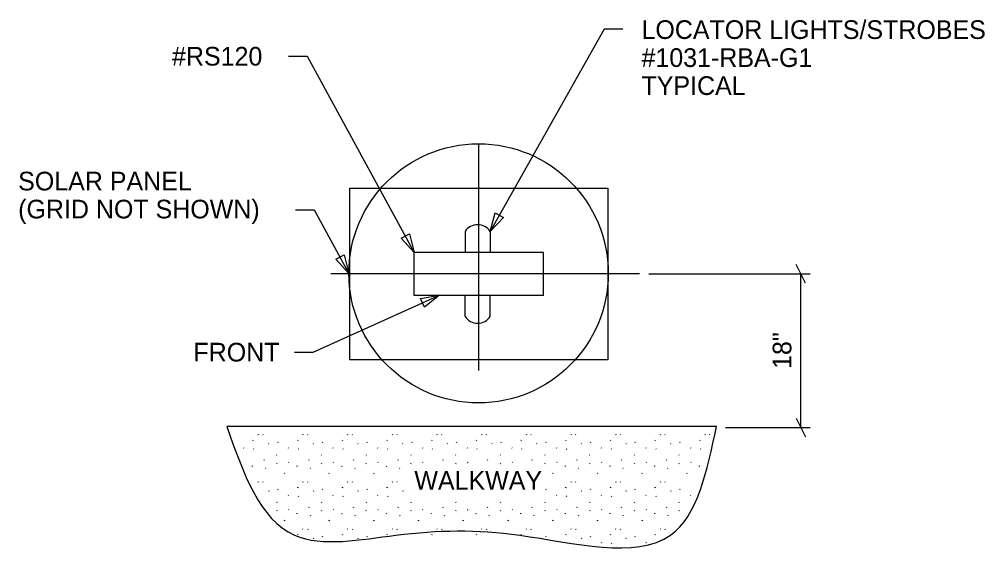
# Model space of a CAD drawing. Extents: x 10097.7 to 10174.5, y 10050.6 to 10139.4.
# Drawn here: x 10101.45 to 10135.89, y 10120.08 to 10139.38 of the extents above; entities that cross this region are included whole.
import ezdxf

# ---------------------------------------------------------------- set-up
doc = ezdxf.new("R2010")
doc.units = 0
for name, color, linetype in [('Level 57', 7, 'Continuous'), ('Level 60', 7, 'Continuous'), ('Level 61', 7, 'Continuous'), ('Level 62', 7, 'Continuous'), ('Level 63', 7, 'Continuous')]:
    doc.layers.add(name, color=color, linetype=linetype)

msp = doc.modelspace()

# ---------------------------------------------------------------- linework, layer by layer
at = {"layer": 'Level 57'}
for p, q in [((10129.491, 10129.949), (10129.157, 10130.616)), ((10123.902, 10130.282), (10129.657, 10130.282)), ((10129.324, 10124.803), (10129.324, 10130.282)), ((10129.157, 10125.136), (10129.491, 10124.47)), ((10126.642, 10124.803), (10129.657, 10124.803))]:
    msp.add_line(p, q, dxfattribs=at)
at = {"layer": 'Level 60'}
for p, q in [((10126.323, 10124.837), (10108.845, 10124.837)), ((10109.783, 10124.333), (10109.795, 10124.36)), ((10109.96, 10124.555), (10109.972, 10124.537)), ((10110.13, 10124.548), (10110.142, 10124.53)), ((10111.377, 10124.333), (10111.389, 10124.36)), ((10111.554, 10124.555), (10111.566, 10124.537)), ((10111.725, 10124.548), (10111.737, 10124.53)), ((10112.972, 10124.333), (10112.984, 10124.36)), ((10113.148, 10124.555), (10113.16, 10124.537)), ((10113.319, 10124.548), (10113.331, 10124.53)), ((10114.566, 10124.333), (10114.578, 10124.36)), ((10114.743, 10124.555), (10114.755, 10124.537)), ((10114.913, 10124.548), (10114.925, 10124.53)), ((10116.16, 10124.333), (10116.172, 10124.36)), ((10116.337, 10124.555), (10116.349, 10124.537)), ((10116.508, 10124.548), (10116.52, 10124.53)), ((10117.755, 10124.333), (10117.767, 10124.36)), ((10117.931, 10124.555), (10117.943, 10124.537)), ((10118.102, 10124.548), (10118.114, 10124.53)), ((10119.349, 10124.333), (10119.361, 10124.36)), ((10119.526, 10124.555), (10119.538, 10124.537)), ((10119.696, 10124.548), (10119.708, 10124.53)), ((10120.943, 10124.333), (10120.955, 10124.36)), ((10121.12, 10124.555), (10121.132, 10124.537)), ((10121.291, 10124.548), (10121.303, 10124.53)), ((10122.538, 10124.333), (10122.55, 10124.36)), ((10122.714, 10124.555), (10122.726, 10124.537)), ((10122.885, 10124.548), (10122.897, 10124.53)), ((10124.132, 10124.333), (10124.144, 10124.36)), ((10124.309, 10124.555), (10124.321, 10124.537)), ((10124.479, 10124.548), (10124.491, 10124.53)), ((10125.726, 10124.333), (10125.738, 10124.36)), ((10125.903, 10124.555), (10125.915, 10124.537)), ((10126.074, 10124.548), (10126.086, 10124.53)), ((10109.447, 10124.072), (10109.459, 10124.054)), ((10109.801, 10124.04), (10109.813, 10124.022)), ((10110.332, 10124.229), (10110.344, 10124.211)), ((10110.667, 10124.264), (10110.679, 10124.291)), ((10111.042, 10124.072), (10111.054, 10124.054)), ((10111.396, 10124.04), (10111.408, 10124.022)), ((10111.926, 10124.229), (10111.938, 10124.211)), ((10112.261, 10124.264), (10112.273, 10124.291)), ((10112.636, 10124.072), (10112.648, 10124.054)), ((10112.99, 10124.04), (10113.002, 10124.022)), ((10113.52, 10124.229), (10113.532, 10124.211)), ((10113.856, 10124.264), (10113.868, 10124.291)), ((10114.23, 10124.072), (10114.242, 10124.054)), ((10114.584, 10124.04), (10114.596, 10124.022)), ((10115.115, 10124.229), (10115.127, 10124.211)), ((10115.45, 10124.264), (10115.462, 10124.291)), ((10115.825, 10124.072), (10115.837, 10124.054)), ((10116.179, 10124.04), (10116.191, 10124.022)), ((10116.709, 10124.229), (10116.721, 10124.211)), ((10117.044, 10124.264), (10117.056, 10124.291)), ((10117.419, 10124.072), (10117.431, 10124.054)), ((10117.773, 10124.04), (10117.785, 10124.022)), ((10118.303, 10124.229), (10118.315, 10124.211)), ((10118.639, 10124.264), (10118.651, 10124.291)), ((10119.013, 10124.072), (10119.025, 10124.054)), ((10119.367, 10124.04), (10119.379, 10124.022)), ((10119.898, 10124.229), (10119.91, 10124.211)), ((10120.233, 10124.264), (10120.245, 10124.291)), ((10120.608, 10124.072), (10120.62, 10124.054)), ((10120.962, 10124.04), (10120.974, 10124.022)), ((10121.492, 10124.229), (10121.504, 10124.211)), ((10121.827, 10124.264), (10121.839, 10124.291)), ((10122.202, 10124.072), (10122.214, 10124.054)), ((10122.556, 10124.04), (10122.568, 10124.022)), ((10123.086, 10124.229), (10123.098, 10124.211)), ((10123.422, 10124.264), (10123.434, 10124.291)), ((10123.796, 10124.072), (10123.808, 10124.054)), ((10124.15, 10124.04), (10124.162, 10124.022)), ((10124.681, 10124.229), (10124.693, 10124.211)), ((10125.016, 10124.264), (10125.028, 10124.291)), ((10125.391, 10124.072), (10125.403, 10124.054)), ((10125.745, 10124.04), (10125.757, 10124.022)), ((10110.181, 10123.626), (10110.193, 10123.653)), ((10110.627, 10123.827), (10110.639, 10123.809)), ((10111.776, 10123.626), (10111.788, 10123.653)), ((10112.221, 10123.827), (10112.233, 10123.809)), ((10113.37, 10123.626), (10113.382, 10123.653)), ((10113.816, 10123.827), (10113.828, 10123.809)), ((10114.964, 10123.626), (10114.976, 10123.653)), ((10115.41, 10123.827), (10115.422, 10123.809)), ((10116.559, 10123.626), (10116.571, 10123.653)), ((10117.004, 10123.827), (10117.016, 10123.809)), ((10118.153, 10123.626), (10118.165, 10123.653)), ((10118.599, 10123.827), (10118.611, 10123.809)), ((10119.747, 10123.626), (10119.759, 10123.653)), ((10120.193, 10123.827), (10120.205, 10123.809)), ((10121.342, 10123.626), (10121.354, 10123.653)), ((10121.787, 10123.827), (10121.799, 10123.809)), ((10122.936, 10123.626), (10122.948, 10123.653)), ((10123.382, 10123.827), (10123.394, 10123.809)), ((10124.53, 10123.626), (10124.542, 10123.653)), ((10124.976, 10123.827), (10124.988, 10123.809)), ((10109.755, 10123.428), (10109.758, 10123.401)), ((10110.225, 10123.348), (10110.237, 10123.33)), ((10110.637, 10123.503), (10110.649, 10123.53)), ((10111.053, 10123.561), (10111.065, 10123.543)), ((10111.35, 10123.428), (10111.353, 10123.401)), ((10111.819, 10123.348), (10111.831, 10123.33)), ((10112.231, 10123.503), (10112.243, 10123.53)), ((10112.647, 10123.561), (10112.659, 10123.543)), ((10112.944, 10123.428), (10112.947, 10123.401)), ((10113.414, 10123.348), (10113.426, 10123.33)), ((10113.826, 10123.503), (10113.838, 10123.53)), ((10114.242, 10123.561), (10114.254, 10123.543)), ((10114.538, 10123.428), (10114.541, 10123.401)), ((10115.008, 10123.348), (10115.02, 10123.33)), ((10115.42, 10123.503), (10115.432, 10123.53)), ((10115.836, 10123.561), (10115.848, 10123.543)), ((10117.014, 10123.503), (10117.026, 10123.53)), ((10117.43, 10123.561), (10117.442, 10123.543)), ((10118.609, 10123.503), (10118.621, 10123.53)), ((10119.025, 10123.561), (10119.037, 10123.543)), ((10120.203, 10123.503), (10120.215, 10123.53)), ((10120.619, 10123.561), (10120.631, 10123.543)), ((10120.916, 10123.428), (10120.919, 10123.401)), ((10121.385, 10123.348), (10121.397, 10123.33)), ((10121.797, 10123.503), (10121.809, 10123.53)), ((10122.213, 10123.561), (10122.225, 10123.543)), ((10122.51, 10123.428), (10122.513, 10123.401)), ((10122.98, 10123.348), (10122.992, 10123.33)), ((10123.392, 10123.503), (10123.404, 10123.53)), ((10123.808, 10123.561), (10123.82, 10123.543)), ((10124.104, 10123.428), (10124.107, 10123.401)), ((10124.574, 10123.348), (10124.586, 10123.33)), ((10124.986, 10123.503), (10124.998, 10123.53)), ((10125.402, 10123.561), (10125.414, 10123.543)), ((10125.699, 10123.428), (10125.702, 10123.401)), ((10110.91, 10123.155), (10110.922, 10123.182)), ((10112.504, 10123.155), (10112.516, 10123.182)), ((10114.098, 10123.155), (10114.11, 10123.182)), ((10120.476, 10123.155), (10120.488, 10123.182)), ((10122.07, 10123.155), (10122.082, 10123.182)), ((10123.664, 10123.155), (10123.676, 10123.182)), ((10125.259, 10123.155), (10125.271, 10123.182)), ((10109.96, 10122.869), (10109.972, 10122.851)), ((10110.13, 10122.862), (10110.142, 10122.844)), ((10110.667, 10122.578), (10110.679, 10122.605)), ((10111.377, 10122.647), (10111.389, 10122.674)), ((10111.554, 10122.869), (10111.566, 10122.851)), ((10111.725, 10122.862), (10111.737, 10122.844)), ((10112.261, 10122.578), (10112.273, 10122.605)), ((10112.972, 10122.647), (10112.984, 10122.674)), ((10113.148, 10122.869), (10113.16, 10122.851)), ((10113.319, 10122.862), (10113.331, 10122.844)), ((10113.856, 10122.578), (10113.868, 10122.605)), ((10114.566, 10122.647), (10114.578, 10122.674)), ((10114.743, 10122.869), (10114.755, 10122.851)), ((10114.913, 10122.862), (10114.925, 10122.844)), ((10120.233, 10122.578), (10120.245, 10122.605)), ((10120.943, 10122.647), (10120.955, 10122.674)), ((10121.12, 10122.869), (10121.132, 10122.851)), ((10121.291, 10122.862), (10121.303, 10122.844)), ((10121.827, 10122.578), (10121.839, 10122.605)), ((10122.538, 10122.647), (10122.55, 10122.674)), ((10122.714, 10122.869), (10122.726, 10122.851)), ((10122.885, 10122.862), (10122.897, 10122.844)), ((10123.422, 10122.578), (10123.434, 10122.605)), ((10124.132, 10122.647), (10124.144, 10122.674)), ((10124.309, 10122.869), (10124.321, 10122.851)), ((10124.479, 10122.862), (10124.491, 10122.844)), ((10125.016, 10122.578), (10125.028, 10122.605)), ((10110.332, 10122.543), (10110.344, 10122.525)), ((10111.042, 10122.386), (10111.054, 10122.368)), ((10111.396, 10122.353), (10111.408, 10122.335)), ((10111.926, 10122.543), (10111.938, 10122.525)), ((10112.636, 10122.386), (10112.648, 10122.368)), ((10112.99, 10122.353), (10113.002, 10122.335)), ((10113.52, 10122.543), (10113.532, 10122.525)), ((10114.23, 10122.386), (10114.242, 10122.368)), ((10114.584, 10122.353), (10114.596, 10122.335)), ((10115.115, 10122.543), (10115.127, 10122.525)), ((10120.608, 10122.386), (10120.62, 10122.368)), ((10120.962, 10122.353), (10120.974, 10122.335)), ((10121.492, 10122.543), (10121.504, 10122.525)), ((10122.202, 10122.386), (10122.214, 10122.368)), ((10122.556, 10122.353), (10122.568, 10122.335)), ((10123.086, 10122.543), (10123.098, 10122.525)), ((10123.796, 10122.386), (10123.808, 10122.368)), ((10124.15, 10122.353), (10124.162, 10122.335)), ((10124.681, 10122.543), (10124.693, 10122.525)), ((10125.391, 10122.386), (10125.403, 10122.368)), ((10110.627, 10122.141), (10110.639, 10122.123)), ((10111.776, 10121.939), (10111.788, 10121.966)), ((10112.221, 10122.141), (10112.233, 10122.123)), ((10113.37, 10121.939), (10113.382, 10121.966)), ((10113.816, 10122.141), (10113.828, 10122.123)), ((10114.964, 10121.939), (10114.976, 10121.966)), ((10115.41, 10122.141), (10115.422, 10122.123)), ((10116.559, 10121.939), (10116.571, 10121.966)), ((10117.004, 10122.141), (10117.016, 10122.123)), ((10118.153, 10121.939), (10118.165, 10121.966)), ((10118.599, 10122.141), (10118.611, 10122.123)), ((10119.747, 10121.939), (10119.759, 10121.966)), ((10120.193, 10122.141), (10120.205, 10122.123)), ((10121.342, 10121.939), (10121.354, 10121.966)), ((10121.787, 10122.141), (10121.799, 10122.123)), ((10122.936, 10121.939), (10122.948, 10121.966)), ((10123.382, 10122.141), (10123.394, 10122.123)), ((10124.53, 10121.939), (10124.542, 10121.966)), ((10124.976, 10122.141), (10124.988, 10122.123)), ((10110.637, 10121.816), (10110.649, 10121.843)), ((10111.053, 10121.875), (10111.065, 10121.857)), ((10111.35, 10121.741), (10111.353, 10121.714)), ((10111.819, 10121.662), (10111.831, 10121.644)), ((10112.231, 10121.816), (10112.243, 10121.843)), ((10112.647, 10121.875), (10112.659, 10121.857)), ((10112.944, 10121.741), (10112.947, 10121.714)), ((10113.414, 10121.662), (10113.426, 10121.644)), ((10113.826, 10121.816), (10113.838, 10121.843)), ((10114.242, 10121.875), (10114.254, 10121.857)), ((10114.538, 10121.741), (10114.541, 10121.714)), ((10115.008, 10121.662), (10115.02, 10121.644)), ((10115.42, 10121.816), (10115.432, 10121.843)), ((10115.836, 10121.875), (10115.848, 10121.857)), ((10116.133, 10121.741), (10116.136, 10121.714)), ((10116.602, 10121.662), (10116.614, 10121.644)), ((10117.014, 10121.816), (10117.026, 10121.843)), ((10117.43, 10121.875), (10117.442, 10121.857)), ((10117.727, 10121.741), (10117.73, 10121.714)), ((10118.197, 10121.662), (10118.209, 10121.644)), ((10118.609, 10121.816), (10118.621, 10121.843)), ((10119.025, 10121.875), (10119.037, 10121.857)), ((10119.321, 10121.741), (10119.324, 10121.714)), ((10119.791, 10121.662), (10119.803, 10121.644)), ((10120.203, 10121.816), (10120.215, 10121.843)), ((10120.619, 10121.875), (10120.631, 10121.857)), ((10120.916, 10121.741), (10120.919, 10121.714)), ((10121.385, 10121.662), (10121.397, 10121.644)), ((10121.797, 10121.816), (10121.809, 10121.843)), ((10122.213, 10121.875), (10122.225, 10121.857)), ((10122.51, 10121.741), (10122.513, 10121.714)), ((10122.98, 10121.662), (10122.992, 10121.644)), ((10123.392, 10121.816), (10123.404, 10121.843)), ((10123.808, 10121.875), (10123.82, 10121.857)), ((10124.104, 10121.741), (10124.107, 10121.714)), ((10124.574, 10121.662), (10124.586, 10121.644)), ((10124.986, 10121.816), (10124.998, 10121.843)), ((10110.91, 10121.469), (10110.922, 10121.496)), ((10112.504, 10121.469), (10112.516, 10121.496)), ((10114.098, 10121.469), (10114.11, 10121.496)), ((10115.693, 10121.469), (10115.705, 10121.496)), ((10117.287, 10121.469), (10117.299, 10121.496)), ((10118.881, 10121.469), (10118.893, 10121.496)), ((10120.476, 10121.469), (10120.488, 10121.496)), ((10122.07, 10121.469), (10122.082, 10121.496)), ((10123.664, 10121.469), (10123.676, 10121.496)), ((10111.377, 10120.96), (10111.389, 10120.987)), ((10111.554, 10121.183), (10111.566, 10121.165)), ((10111.725, 10121.176), (10111.737, 10121.158)), ((10111.926, 10120.856), (10111.938, 10120.838)), ((10112.261, 10120.891), (10112.273, 10120.918)), ((10112.972, 10120.96), (10112.984, 10120.987)), ((10113.148, 10121.183), (10113.16, 10121.165)), ((10113.319, 10121.176), (10113.331, 10121.158)), ((10113.52, 10120.856), (10113.532, 10120.838)), ((10113.856, 10120.891), (10113.868, 10120.918)), ((10114.566, 10120.96), (10114.578, 10120.987)), ((10114.743, 10121.183), (10114.755, 10121.165)), ((10114.913, 10121.176), (10114.925, 10121.158)), ((10116.16, 10120.96), (10116.172, 10120.987)), ((10116.337, 10121.183), (10116.349, 10121.165)), ((10116.508, 10121.176), (10116.52, 10121.158)), ((10117.755, 10120.96), (10117.767, 10120.987)), ((10117.931, 10121.183), (10117.943, 10121.165)), ((10118.102, 10121.176), (10118.114, 10121.158)), ((10119.349, 10120.96), (10119.361, 10120.987)), ((10119.526, 10121.183), (10119.538, 10121.165)), ((10119.696, 10121.176), (10119.708, 10121.158)), ((10120.233, 10120.891), (10120.245, 10120.918)), ((10120.943, 10120.96), (10120.955, 10120.987)), ((10121.12, 10121.183), (10121.132, 10121.165)), ((10121.291, 10121.176), (10121.303, 10121.158)), ((10121.492, 10120.856), (10121.504, 10120.838)), ((10121.827, 10120.891), (10121.839, 10120.918)), ((10122.538, 10120.96), (10122.55, 10120.987)), ((10122.714, 10121.183), (10122.726, 10121.165)), ((10122.885, 10121.176), (10122.897, 10121.158)), ((10123.086, 10120.856), (10123.098, 10120.838)), ((10123.422, 10120.891), (10123.434, 10120.918)), ((10124.132, 10120.96), (10124.144, 10120.987)), ((10124.309, 10121.183), (10124.321, 10121.165)), ((10124.479, 10121.176), (10124.491, 10121.158)), ((10122.202, 10120.7), (10122.214, 10120.682)), ((10122.556, 10120.667), (10122.568, 10120.649)), ((10123.796, 10120.7), (10123.808, 10120.682))]:
    msp.add_line(p, q, dxfattribs=at)
msp.add_spline([(10108.845, 10124.837), (10111.266, 10120.951), (10114.878, 10120.951), (10119.3, 10120.951), (10124.68, 10120.951), (10126.323, 10124.837)], degree=3, dxfattribs=at)
at = {"layer": 'Level 61'}
for p, q in [((10117.84, 10126.838), (10117.84, 10134.935)), ((10120.142, 10131.052), (10115.538, 10131.052)), ((10115.538, 10129.515), (10115.538, 10131.052)), ((10120.142, 10129.515), (10120.142, 10131.052)), ((10123.569, 10130.282), (10112.557, 10130.282)), ((10120.142, 10129.515), (10115.538, 10129.515))]:
    msp.add_line(p, q, dxfattribs=at)
for centre, radius in [((10117.831, 10130.303), 4.626), ((10117.84, 10130.295), 0.0124)]:
    msp.add_circle(centre, radius, dxfattribs=at)
at = {"layer": 'Level 62'}
for p, q in [((10113.236, 10127.215), (10113.236, 10133.35)), ((10113.236, 10133.35), (10122.444, 10133.35)), ((10122.444, 10133.35), (10122.444, 10127.215)), ((10117.35, 10131.799), (10117.35, 10131.049)), ((10118.246, 10131.799), (10118.246, 10131.049)), ((10117.35, 10128.766), (10117.35, 10129.515)), ((10118.246, 10128.766), (10118.246, 10129.515)), ((10122.444, 10127.215), (10113.236, 10127.215))]:
    msp.add_line(p, q, dxfattribs=at)
for centre, start, end in [((10117.798, 10131.505), 33.26, 146.74), ((10117.798, 10129.06), 213.26, 326.74)]:
    msp.add_arc(centre, 0.536, start, end, dxfattribs=at)
at = {"layer": 'Level 63'}
for p, q in [((10122.311, 10139.02), (10118.246, 10131.799)), ((10122.977, 10139.02), (10122.311, 10139.02)), ((10111.044, 10138.056), (10111.711, 10138.056)), ((10111.711, 10138.056), (10115.538, 10131.052)), ((10111.3, 10132.577), (10111.967, 10132.577)), ((10111.967, 10132.577), (10113.205, 10130.303)), ((10111.931, 10127.488), (10116.438, 10129.528)), ((10111.265, 10127.488), (10111.931, 10127.488))]:
    msp.add_line(p, q, dxfattribs=at)
for points in [[(10118.718, 10132.298), (10118.246, 10131.799), (10118.428, 10132.461)], [(10115.365, 10131.717), (10115.538, 10131.052), (10115.072, 10131.557)], [(10113.033, 10130.969), (10113.205, 10130.303), (10112.74, 10130.809)], [(10115.762, 10129.405), (10116.438, 10129.528), (10115.9, 10129.101)]]:
    msp.add_lwpolyline(points, close=True, dxfattribs=at)

# ---------------------------------------------------------------- texts
at = {"layer": 'Level 57'}
msp.add_text('18"', height=0.6667, rotation=90, dxfattribs=at).set_placement((10128.991, 10126.891))
at = {"layer": 'Level 63'}
for s, height, p in [('LOCATOR LIGHTS/STROBES', 0.66667, (10123.644, 10138.674)), ('#RS120', 0.6667, (10106.895, 10137.723)), ('#1031-RBA-G1', 0.66667, (10123.644, 10137.674)), ('TYPICAL', 0.6667, (10123.644, 10136.674)), ('SOLAR PANEL', 0.66667, (10101.405, 10133.265)), ('(GRID NOT SHOWN)', 0.66667, (10101.405, 10132.265)), ('FRONT', 0.6667, (10107.658, 10127.155)), ('WALKWAY', 0.6667, (10115.54, 10122.575))]:
    msp.add_text(s, height=height, dxfattribs=at).set_placement(p)

doc.saveas('drawing.dxf')
